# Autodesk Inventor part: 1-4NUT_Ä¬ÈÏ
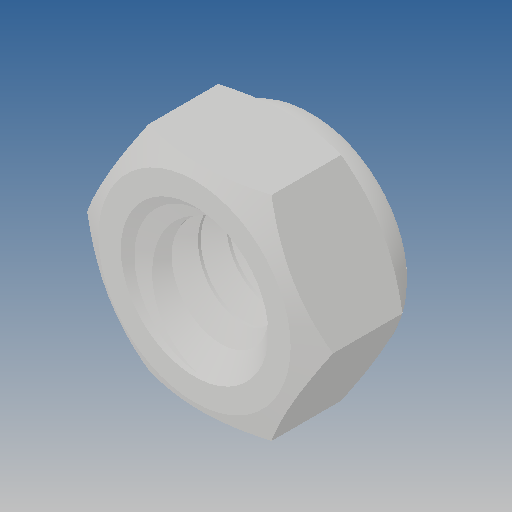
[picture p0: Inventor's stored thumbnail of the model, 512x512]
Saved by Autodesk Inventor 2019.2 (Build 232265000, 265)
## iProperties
Created: 2010-06
Part Number: 1-4NUT_Ä¬ÈÏ
Material: Ogólny
Document SubType Name: Modeling
Designer: CADENGINEERING4
Density: 1 g/cm^3
Appearance: Domyślna
Author: CADENGINEERING4
Revision Number: ÈÎºÎ
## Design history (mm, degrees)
feature "NONE"
node "Bryła1"
